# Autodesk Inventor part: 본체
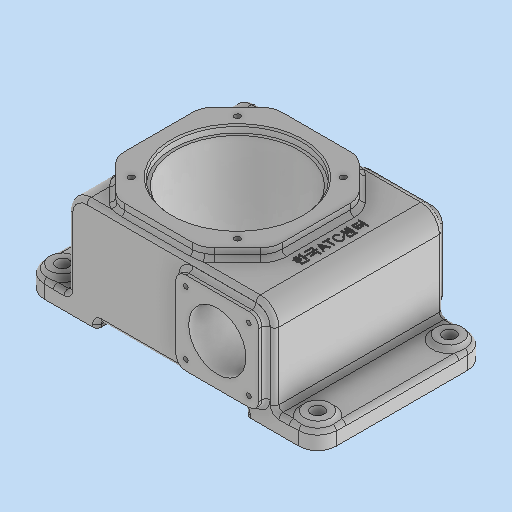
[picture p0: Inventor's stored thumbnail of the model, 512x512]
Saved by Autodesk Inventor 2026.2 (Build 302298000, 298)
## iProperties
Created: 2026-02
Part Number: 본체
Material: 일반
Document SubType Name: Modeling
Designer: PC2-07
Density: 1 g/cm^3
Appearance: 기본값
Mass: 851.849 g
Surface Area: 1198.33 cm^2
Volume: 851.849 cm^3
Author: PC2-07
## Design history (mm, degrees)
sketch "스케치1"
  geometry: L1 (102, -59)-(-102, -59); L2 (-102, -59)-(-102, 59); L3 (-102, 59)-(102, 59); L4 (102, 59)-(102, -59); L5 (102, -59)-(-102, 59); L6 (-102, -59)-(102, 59); L7 (-52, 59)-(-52, -59); L8 (52, 59)-(52, -59); 1 further point
  constraints: 16 end point, 4 point on line, 3 perpendicular, 2 midpoint, 2 parallel, 1 horizontal
  dimensions: "d0" = 118 distance between parallel lines of L1 L3; "d1" = 204 distance between parallel lines of L4 L2; "d2" = 50 distance between parallel lines of L2 L7; "d3" = 50 distance between parallel lines of L4 L8
extrude "돌출1" new body sketch "스케치1" distance "d4" = 12; taper "d5" = 0 deg
node "작업 평면1"
sketch "스케치2"
  geometry: L1 (72, -59)-(-72, -59); L2 (-72, -59)-(-72, 59); L3 (-72, 59)-(72, 59); L4 (72, 59)-(72, -59); L5 (72, -59)-(-72, 59); L6 (-72, -59)-(72, 59); 1 further point
  constraints: 12 end point, 2 midpoint, 2 parallel, 1 horizontal, 1 perpendicular
  dimensions: "d7" = 118 distance between parallel lines of L1 L3; "d8" = 144 distance between parallel lines of L4 L2
extrude "돌출2" join sketch "스케치2" distance "d9" = 70; taper "d10" = 0 deg
node "작업 평면2"
sketch "스케치3"
  geometry: L1 (-8, 69)-(-66, 69); L2 (-66, 69)-(-66, 11); L3 (-66, 11)-(-8, 11); L4 (-8, 11)-(-8, 69); L5 (-8, 69)-(-66, 11); L6 (-66, 69)-(-8, 11); L7 (-102, 0)-(-102, 12) reference; 2 further points
  constraints: 12 end point, 2 midpoint, 2 parallel, 1 horizontal, 1 perpendicular
  dimensions: "d12" = 40 vertical distance of point (0, 0) point (-37, 40); "d13" = 58 distance between parallel lines of L3 L1; "d14" = 58 distance between parallel lines of L4 L2; "d129" = 65 distance from line of point (-37, 40) L7
extrude "돌출3" join sketch "스케치3" distance "d15" = 128; taper "d16" = 0 deg
sketch "스케치4"
  geometry: L1 (-68, -30)-(-68, 30); L2 (-68, 22.782)-(-35.782, 55); L3 (-43, 55)-(17, 55); L4 (9.782, 55)-(42, 22.782); L5 (42, 30)-(42, -30); L6 (42, -22.782)-(9.782, -55); L7 (17, -55)-(-43, -55); L8 (-35.782, -55)-(-68, -22.782); L9 (42, -30)-(17, -55); L10 (-68, -30)-(-43, -55); L11 (-68, 30)-(-43, 55); L12 (17, 55)-(42, 30); L13 (102, -59)-(102, 59) reference; 6 further points
  constraints: 24 end point, 16 point on line, 1 horizontal alignment, 1 midpoint, 1 vertical, 17 other
  dimensions: "d17" = 110 distance between parallel lines of L7 L3; "d18" = 25 distance of L5.end point (42, -55); "d19" = 25 distance of L7.start point (42, -55) (= d18); "d20" = 25 distance of L1.start point (-68, -55); "d21" = 25 distance of L7.end point (-68, -55) (= d20); "d22" = 25 distance of L1.end point (-68, 55) (= d20); "d23" = 25 distance of L3.start point (-68, 55) (= d22); "d24" = 25 distance of L3.end point (42, 55) (= d20); "d25" = 25 distance of L5.start point (42, 55) (= d24); "d97" = 115 distance from line of L13 point (-13, 0)
extrude "돌출4" join sketch "스케치4" distance "d26" = 7; taper "d27" = 0 deg
sketch "스케치5"
  geometry: L1 (102, -59)-(102, 59) reference; C1 r 9 at (89, -46); 1 further point
  constraints: 1 centre point
  dimensions: "d28" = 18 diameter of C1; "d29" = 46 vertical distance of C1.centre point (0, 0); "d123" = 13 distance from line of C1.centre L1
extrude "돌출5" join sketch "스케치5" distance "d31" = 3; taper "d32" = 0 deg
sketch "스케치6"
  geometry: C1 r 9 at (0, 0) reference; 2 further points
  constraints: 1 coincident
hole "구멍1" sketch "스케치6" at (0, 0) diameter "d33" = 9; stored, may be unused: countersink angle "d37" = 90 deg, drill point angle "d39" = 120 deg; dims "d34" = 6, "d35" = 4, "d36" = 2, "d38" = 10
sketch "스케치7"
  geometry: L1 (8, 11)-(8, 69) reference; 2 further points
  dimensions: "d46" = 40 vertical distance of point (0, 0) point (37, 40); "d47" = 29 distance from line of L1 point (37, 40)
hole "구멍2" sketch "스케치7" at (37, 40) diameter "d48" = 40; stored, may be unused: countersink angle "d52" = 90 deg, drill point angle "d54" = 120 deg; dims "d49" = 6, "d50" = 4, "d51" = 2, "d53" = 8
sketch "스케치8"
  geometry: L1 (13, 82)-(13, 11); L2 (13, 11)-(-7, 11); L3 (-66, 11)-(-8, 11) reference; L4 (-7, 11)-(-7, 22); L5 (-7, 22)-(-12, 22); L6 (-12, 22)-(-18, 16); L7 (-18, 16)-(-30, 16); L8 (-30, 16)-(-30, 77); L9 (-30, 77)-(-32, 77); L10 (-32, 77)-(-32, 82); L11 (-32, 82)-(13, 82); L12 (-42, 82)-(-17, 82) reference; L13 (-17, 82)-(43, 82) reference; 1 further point
  constraints: 20 end point, 5 perpendicular, 2 collinear, 1 midpoint, 1 parallel, 1 vertical
  dimensions: "d55" = 40 diameter of L4 L1; "d58" = 50 diameter of L5.end L1; "d59" = 5 distance between parallel lines of L11 L9; "d60" = 90 diameter of L10 L1; "d61" = 86 diameter of L8 L1; "d62" = 45 deg angle of L4 L6; "d63" = 66 distance between parallel lines of L7 L11; "d64" = 6 distance between parallel lines of L5 L7; "d65" = 11 distance between parallel lines of L5 L2
revolve "회전1" sketch "스케치8" stored, may be unused: angle "d66" = 90 deg
sketch "스케치9"
  geometry: C1 r 20 at (37, 40) reference; 2 further points
  dimensions: "d67" = 22 horizontal distance of C1.centre point (15, 62); "d68" = 22 horizontal distance of C1.centre point (15, 62)
hole "구멍3" sketch "스케치9" at (15, 62) diameter "d69" = 3.242; stored, may be unused: countersink angle "d73" = 90 deg, drill point angle "d75" = 118 deg; dims "d70" = 8, "d71" = 4, "d72" = 2, "d74" = 10
sketch "스케치10"
  geometry: C1 r 20 at (-13, 0) reference; 2 further points
  dimensions: "d98" = 37 horizontal distance of point (-50, -37) C1.centre; "d99" = 37 horizontal distance of point (-50, -37) C1.centre
hole "구멍4" sketch "스케치10" at (-50, -37) diameter "d84" = 4.134; stored, may be unused: countersink angle "d88" = 90 deg, drill point angle "d90" = 118 deg; dims "d85" = 10, "d86" = 4, "d87" = 2, "d89" = 12
fillet "모깎기5" dims "d112" = 13
chamfer "모따기1" distance "d105" = 1; stored, may be unused: second distance "d106" = 2, angle "d107" = 45 deg
fillet "모깎기1" dims "d108" = 1.5
fillet "모깎기2" dims "d109" = 3
fillet "모깎기3" dims "d110" = 15
fillet "모깎기4" dims "d111" = 13
fillet "모깎기6" dims "d113" = 3
fillet "모깎기7" dims "d114" = 3
fillet "모깎기9" dims "d116" = 3
fillet "모깎기10" dims "d117" = 3
fillet "모깎기11" dims "d118" = 3
fillet "모깎기12" dims "d119" = 3
fillet "모깎기13" dims "d120" = 7
fillet "모깎기15" dims "d122" = 3
sketch "스케치12"
  geometry: L1 (48.5, -22.5)-(48.5, 22.5); L2 (48.5, 22.5)-(55.5, 22.5); L3 (55.5, 22.5)-(55.5, -22.5); L4 (55.5, -22.5)-(48.5, -22.5); L5 (52, -22.5)-(52, 22.5); L6 (48.5, 0)-(55.5, 0); C1 r 20 at (-13, 0) reference; 3 further points
  constraints: 6 midpoint, 4 end point, 1 horizontal alignment, 2 other
  dimensions: "d124" = 45 distance of L2.end L3.end; "d125" = 7 distance of L3.end L1.start; "d126" = 65 distance of point (52, 0) C1.centre
feature "엠보싱2" sketch "스케치12" dims "d127" = 0.5, "d128" = 0
fillet "모깎기16" dims "d130" = 2.9
node "솔리드1"
pattern_linear "직사각형 패턴1" dims "d42" = 178, "d45" = 92
pattern_linear "직사각형 패턴2" dims "d78" = 44, "d81" = 44
mirror "미러1"
pattern_linear "직사각형 패턴3" dims "d93" = 74, "d96" = 74
feature "A9D066F2-1C7D-4E18-AEED-F7BC21143FA4" dims "d33" = 9, "d34" = 6, "d35" = 4, "d36" = 2, "d37" = 90 deg, "d38" = 10, "d39" = 120 deg
other parameters: "d6" = 5, "d11" = -64
